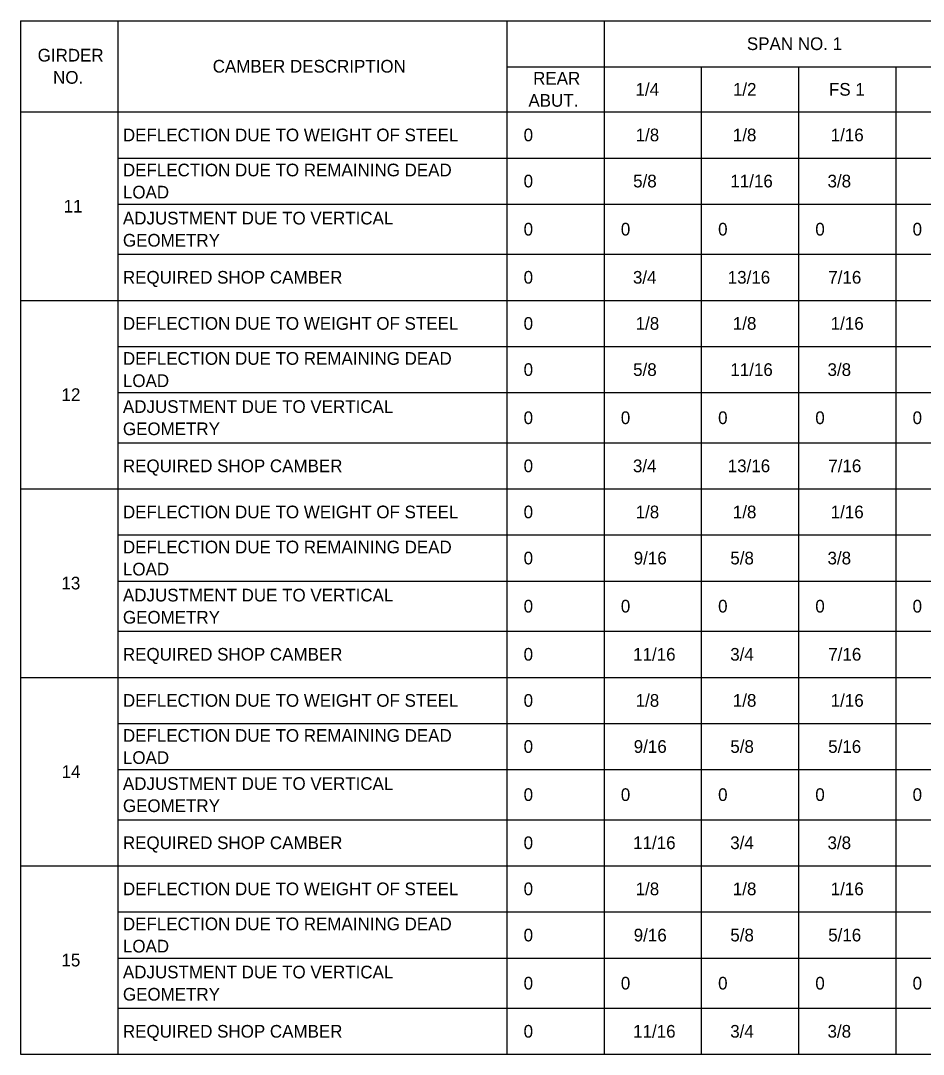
# Model space of a CAD drawing. Extents: x 4.1 to 33.4, y -25.9 to 16.7.
# Drawn here: x 4.06 to 13.44, y 3.01 to 13.75 of the extents above; entities that cross this region are included whole.
import ezdxf

# ---------------------------------------------------------------- set-up
doc = ezdxf.new("R2010")
doc.units = 0
doc.layers.add('BR_X_Slab_Const_Joint', color=7, linetype='Continuous')
doc.layers.add('SH_Border', color=7, linetype='Continuous')

msp = doc.modelspace()

# ---------------------------------------------------------------- linework, layer by layer
at = {"layer": 'SH_Border'}
for p, q in [((4.061, 13.749), (7.093, 13.749)), ((4.061, 13.749), (4.061, 10.843)), ((5.072, 13.749), (5.072, 10.843)), ((7.093, 13.749), (12.145, 13.749)), ((9.114, 13.749), (9.114, 10.843)), ((10.124, 13.749), (10.124, 10.843)), ((12.145, 13.749), (13.155, 13.749)), ((13.155, 13.749), (16.186, 13.749)), ((9.114, 13.27), (12.145, 13.27)), ((11.134, 13.27), (11.134, 10.843)), ((12.145, 13.27), (13.155, 13.27)), ((12.145, 13.27), (12.145, 10.843)), ((13.155, 13.27), (16.186, 13.27)), ((13.155, 13.27), (13.155, 10.843)), ((4.061, 12.801), (7.093, 12.801)), ((7.093, 12.801), (12.145, 12.801)), ((12.145, 12.801), (13.155, 12.801)), ((13.155, 12.801), (16.186, 12.801)), ((5.072, 12.322), (7.093, 12.322)), ((7.093, 12.322), (12.145, 12.322)), ((12.145, 12.322), (13.155, 12.322)), ((13.155, 12.322), (16.186, 12.322)), ((5.072, 11.843), (7.093, 11.843)), ((7.093, 11.843), (12.145, 11.843)), ((12.145, 11.843), (13.155, 11.843)), ((13.155, 11.843), (16.186, 11.843)), ((5.072, 11.322), (7.093, 11.322)), ((7.093, 11.322), (12.145, 11.322)), ((12.145, 11.322), (13.155, 11.322)), ((13.155, 11.322), (16.186, 11.322)), ((4.061, 10.843), (7.093, 10.843)), ((4.061, 10.843), (4.061, 10.124)), ((5.072, 10.843), (5.072, 10.124)), ((7.093, 10.843), (12.145, 10.843)), ((9.114, 10.843), (9.114, 10.124)), ((10.124, 10.843), (10.124, 10.124)), ((11.134, 10.843), (11.134, 10.124)), ((12.145, 10.843), (13.155, 10.843)), ((12.145, 10.843), (12.145, 10.124)), ((13.155, 10.843), (16.186, 10.843)), ((13.155, 10.843), (13.155, 10.124)), ((5.072, 10.364), (7.093, 10.364)), ((7.093, 10.364), (12.145, 10.364)), ((12.145, 10.364), (13.155, 10.364)), ((13.155, 10.364), (16.186, 10.364)), ((4.061, 10.124), (4.061, 8.166)), ((5.072, 10.124), (5.072, 8.166)), ((9.114, 10.124), (9.114, 8.166)), ((10.124, 10.124), (10.124, 8.166)), ((11.134, 10.124), (11.134, 8.166)), ((12.145, 10.124), (12.145, 8.166)), ((13.155, 10.124), (13.155, 8.166)), ((5.072, 9.885), (7.093, 9.885)), ((7.093, 9.885), (12.145, 9.885)), ((12.145, 9.885), (13.155, 9.885)), ((13.155, 9.885), (16.186, 9.885)), ((5.072, 9.364), (7.093, 9.364)), ((7.093, 9.364), (12.145, 9.364)), ((12.145, 9.364), (13.155, 9.364)), ((13.155, 9.364), (16.186, 9.364)), ((4.061, 8.885), (7.093, 8.885)), ((7.093, 8.885), (12.145, 8.885)), ((12.145, 8.885), (13.155, 8.885)), ((13.155, 8.885), (16.186, 8.885)), ((5.072, 8.406), (7.093, 8.406)), ((7.093, 8.406), (12.145, 8.406)), ((12.145, 8.406), (13.155, 8.406)), ((13.155, 8.406), (16.186, 8.406)), ((4.061, 8.166), (4.061, 6.447)), ((5.072, 8.166), (5.072, 6.447)), ((9.114, 8.166), (9.114, 6.447)), ((10.124, 8.166), (10.124, 6.447)), ((11.134, 8.166), (11.134, 6.447)), ((12.145, 8.166), (12.145, 6.447)), ((13.155, 8.166), (13.155, 6.447)), ((5.072, 7.926), (7.093, 7.926)), ((7.093, 7.926), (12.145, 7.926)), ((12.145, 7.926), (13.155, 7.926)), ((13.155, 7.926), (16.186, 7.926)), ((5.072, 7.406), (7.093, 7.406)), ((7.093, 7.406), (12.145, 7.406)), ((12.145, 7.406), (13.155, 7.406)), ((13.155, 7.406), (16.186, 7.406)), ((4.061, 6.926), (7.093, 6.926)), ((7.093, 6.926), (12.145, 6.926)), ((12.145, 6.926), (13.155, 6.926)), ((13.155, 6.926), (16.186, 6.926)), ((4.061, 6.447), (4.061, 4.489)), ((5.072, 6.447), (7.093, 6.447)), ((5.072, 6.447), (5.072, 4.489)), ((7.093, 6.447), (12.145, 6.447)), ((9.114, 6.447), (9.114, 4.489)), ((10.124, 6.447), (10.124, 4.489)), ((11.134, 6.447), (11.134, 4.489)), ((12.145, 6.447), (13.155, 6.447)), ((12.145, 6.447), (12.145, 4.489)), ((13.155, 6.447), (16.186, 6.447)), ((13.155, 6.447), (13.155, 4.489)), ((5.072, 5.968), (7.093, 5.968)), ((7.093, 5.968), (12.145, 5.968)), ((12.145, 5.968), (13.155, 5.968)), ((13.155, 5.968), (16.186, 5.968)), ((5.072, 5.447), (7.093, 5.447)), ((7.093, 5.447), (12.145, 5.447)), ((12.145, 5.447), (13.155, 5.447)), ((13.155, 5.447), (16.186, 5.447)), ((4.061, 4.968), (7.093, 4.968)), ((7.093, 4.968), (12.145, 4.968)), ((12.145, 4.968), (13.155, 4.968)), ((13.155, 4.968), (16.186, 4.968)), ((4.061, 4.489), (4.061, 3.249)), ((5.072, 4.489), (7.093, 4.489)), ((5.072, 4.489), (5.072, 3.249)), ((7.093, 4.489), (12.145, 4.489)), ((9.114, 4.489), (9.114, 3.249)), ((10.124, 4.489), (10.124, 3.249)), ((11.134, 4.489), (11.134, 3.249)), ((12.145, 4.489), (13.155, 4.489)), ((12.145, 4.489), (12.145, 3.249)), ((13.155, 4.489), (16.186, 4.489)), ((13.155, 4.489), (13.155, 3.249)), ((5.072, 4.01), (7.093, 4.01)), ((7.093, 4.01), (12.145, 4.01)), ((12.145, 4.01), (13.155, 4.01)), ((13.155, 4.01), (16.186, 4.01)), ((5.072, 3.489), (7.093, 3.489)), ((7.093, 3.489), (12.145, 3.489)), ((12.145, 3.489), (13.155, 3.489)), ((13.155, 3.489), (16.186, 3.489)), ((4.061, 3.249), (4.061, 3.01)), ((5.072, 3.249), (5.072, 3.01)), ((9.114, 3.249), (9.114, 3.01)), ((10.124, 3.249), (10.124, 3.01)), ((11.134, 3.249), (11.134, 3.01)), ((12.145, 3.249), (12.145, 3.01)), ((13.155, 3.249), (13.155, 3.01)), ((4.061, 3.01), (7.093, 3.01)), ((7.093, 3.01), (12.145, 3.01)), ((12.145, 3.01), (13.155, 3.01)), ((13.155, 3.01), (16.186, 3.01))]:
    msp.add_line(p, q, dxfattribs=at)

# ---------------------------------------------------------------- texts
at = {"layer": 'BR_X_Slab_Const_Joint'}
for s, height, p in [('SPAN NO. 1', 0.1318, (11.608, 13.444)), ('GIRDER', 0.1318, (4.238, 13.325)), ('CAMBER DESCRIPTION', 0.13177, (6.057, 13.21)), ('NO.', 0.1318, (4.398, 13.094)), ('REAR', 0.1318, (9.387, 13.085)), ('  1/4 ', 0.1318, (10.353, 12.97)), ('  1/2 ', 0.1318, (11.365, 12.97)), ('FS 1', 0.1318, (12.461, 12.97)), ('ABUT.', 0.1318, (9.338, 12.855)), ('DEFLECTION DUE TO WEIGHT OF STEEL', 0.13177, (5.124, 12.496)), ('0      ', 0.1318, (9.288, 12.496)), ('  1/8 ', 0.1318, (10.354, 12.496)), ('  1/8 ', 0.1318, (11.364, 12.496)), ('  1/16', 0.1318, (12.381, 12.496)), ('DEFLECTION DUE TO REMAINING DEAD', 0.13177, (5.124, 12.132)), ('0      ', 0.1318, (9.288, 12.017)), ('  5/8 ', 0.1318, (10.328, 12.017)), (' 11/16', 0.1318, (11.387, 12.017)), ('  3/8 ', 0.1318, (12.348, 12.017)), ('LOAD', 0.1318, (5.124, 11.902)), ('11', 0.1318, (4.508, 11.756)), ('ADJUSTMENT DUE TO VERTICAL', 0.13177, (5.124, 11.632)), ('0      ', 0.1318, (9.288, 11.517)), ('0      ', 0.1318, (10.298, 11.517)), ('0      ', 0.1318, (11.309, 11.517)), ('0      ', 0.1318, (12.319, 11.517)), ('0      ', 0.1318, (13.33, 11.517)), ('GEOMETRY', 0.1318, (5.124, 11.402)), ('REQUIRED SHOP CAMBER', 0.13177, (5.124, 11.017)), ('0      ', 0.1318, (9.288, 11.017)), ('  3/4 ', 0.1318, (10.326, 11.017)), (' 13/16', 0.1318, (11.36, 11.017)), ('  7/16', 0.1318, (12.356, 11.017)), ('DEFLECTION DUE TO WEIGHT OF STEEL', 0.13177, (5.124, 10.538)), ('0      ', 0.1318, (9.288, 10.538)), ('  1/8 ', 0.1318, (10.354, 10.538)), ('  1/8 ', 0.1318, (11.364, 10.538)), ('  1/16', 0.1318, (12.381, 10.538)), ('DEFLECTION DUE TO REMAINING DEAD', 0.13177, (5.124, 10.174)), ('0      ', 0.1318, (9.288, 10.058)), ('  5/8 ', 0.1318, (10.328, 10.058)), (' 11/16', 0.1318, (11.387, 10.058)), ('  3/8 ', 0.1318, (12.348, 10.058)), ('LOAD', 0.1318, (5.124, 9.943)), ('12', 0.1318, (4.486, 9.798)), ('ADJUSTMENT DUE TO VERTICAL', 0.13177, (5.124, 9.674)), ('0      ', 0.1318, (9.288, 9.558)), ('0      ', 0.1318, (10.298, 9.558)), ('0      ', 0.1318, (11.309, 9.558)), ('0      ', 0.1318, (12.319, 9.558)), ('0      ', 0.1318, (13.33, 9.558)), ('GEOMETRY', 0.1318, (5.124, 9.443)), ('REQUIRED SHOP CAMBER', 0.13177, (5.124, 9.058)), ('0      ', 0.1318, (9.288, 9.058)), ('  3/4 ', 0.1318, (10.326, 9.058)), (' 13/16', 0.1318, (11.36, 9.058)), ('  7/16', 0.1318, (12.356, 9.058)), ('DEFLECTION DUE TO WEIGHT OF STEEL', 0.13177, (5.124, 8.579)), ('0      ', 0.1318, (9.288, 8.579)), ('  1/8 ', 0.1318, (10.354, 8.579)), ('  1/8 ', 0.1318, (11.364, 8.579)), ('  1/16', 0.1318, (12.381, 8.579)), ('DEFLECTION DUE TO REMAINING DEAD', 0.13177, (5.124, 8.215)), ('0      ', 0.1318, (9.288, 8.1)), ('  9/16', 0.1318, (10.334, 8.1)), ('  5/8 ', 0.1318, (11.338, 8.1)), ('  3/8 ', 0.1318, (12.348, 8.1)), ('LOAD', 0.1318, (5.124, 7.985)), ('13', 0.1318, (4.485, 7.84)), ('ADJUSTMENT DUE TO VERTICAL', 0.13177, (5.124, 7.715)), ('0      ', 0.1318, (9.288, 7.6)), ('0      ', 0.1318, (10.298, 7.6)), ('0      ', 0.1318, (11.309, 7.6)), ('0      ', 0.1318, (12.319, 7.6)), ('0      ', 0.1318, (13.33, 7.6)), ('GEOMETRY', 0.1318, (5.124, 7.485)), ('REQUIRED SHOP CAMBER', 0.13177, (5.124, 7.1)), ('0      ', 0.1318, (9.288, 7.1)), (' 11/16', 0.1318, (10.377, 7.1)), ('  3/4 ', 0.1318, (11.337, 7.1)), ('  7/16', 0.1318, (12.356, 7.1)), ('DEFLECTION DUE TO WEIGHT OF STEEL', 0.13177, (5.124, 6.621)), ('0      ', 0.1318, (9.288, 6.621)), ('  1/8 ', 0.1318, (10.354, 6.621)), ('  1/8 ', 0.1318, (11.364, 6.621)), ('  1/16', 0.1318, (12.381, 6.621)), ('DEFLECTION DUE TO REMAINING DEAD', 0.13177, (5.124, 6.257)), ('0      ', 0.1318, (9.288, 6.142)), ('  9/16', 0.1318, (10.334, 6.142)), ('  5/8 ', 0.1318, (11.338, 6.142)), ('  5/16', 0.1318, (12.355, 6.142)), ('LOAD', 0.1318, (5.124, 6.027)), ('14', 0.1318, (4.487, 5.881)), ('ADJUSTMENT DUE TO VERTICAL', 0.13177, (5.124, 5.757)), ('0      ', 0.1318, (9.288, 5.642)), ('0      ', 0.1318, (10.298, 5.642)), ('0      ', 0.1318, (11.309, 5.642)), ('0      ', 0.1318, (12.319, 5.642)), ('0      ', 0.1318, (13.33, 5.642)), ('GEOMETRY', 0.1318, (5.124, 5.527)), ('REQUIRED SHOP CAMBER', 0.13177, (5.124, 5.142)), ('0      ', 0.1318, (9.288, 5.142)), (' 11/16', 0.1318, (10.377, 5.142)), ('  3/4 ', 0.1318, (11.337, 5.142)), ('  3/8 ', 0.1318, (12.348, 5.142)), ('DEFLECTION DUE TO WEIGHT OF STEEL', 0.13177, (5.124, 4.663)), ('0      ', 0.1318, (9.288, 4.663)), ('  1/8 ', 0.1318, (10.354, 4.663)), ('  1/8 ', 0.1318, (11.364, 4.663)), ('  1/16', 0.1318, (12.381, 4.663)), ('DEFLECTION DUE TO REMAINING DEAD', 0.13177, (5.124, 4.299)), ('0      ', 0.1318, (9.288, 4.183)), ('  9/16', 0.1318, (10.334, 4.183)), ('  5/8 ', 0.1318, (11.338, 4.183)), ('  5/16', 0.1318, (12.355, 4.183)), ('LOAD', 0.1318, (5.124, 4.068)), ('15', 0.1318, (4.485, 3.923)), ('ADJUSTMENT DUE TO VERTICAL', 0.13177, (5.124, 3.799)), ('0      ', 0.1318, (9.288, 3.683)), ('0      ', 0.1318, (10.298, 3.683)), ('0      ', 0.1318, (11.309, 3.683)), ('0      ', 0.1318, (12.319, 3.683)), ('0      ', 0.1318, (13.33, 3.683)), ('GEOMETRY', 0.1318, (5.124, 3.568)), ('REQUIRED SHOP CAMBER', 0.13177, (5.124, 3.183)), ('0      ', 0.1318, (9.288, 3.183)), (' 11/16', 0.1318, (10.377, 3.183)), ('  3/4 ', 0.1318, (11.337, 3.183)), ('  3/8 ', 0.1318, (12.348, 3.183))]:
    msp.add_text(s, height=height, dxfattribs=at).set_placement(p)

doc.saveas('drawing.dxf')
